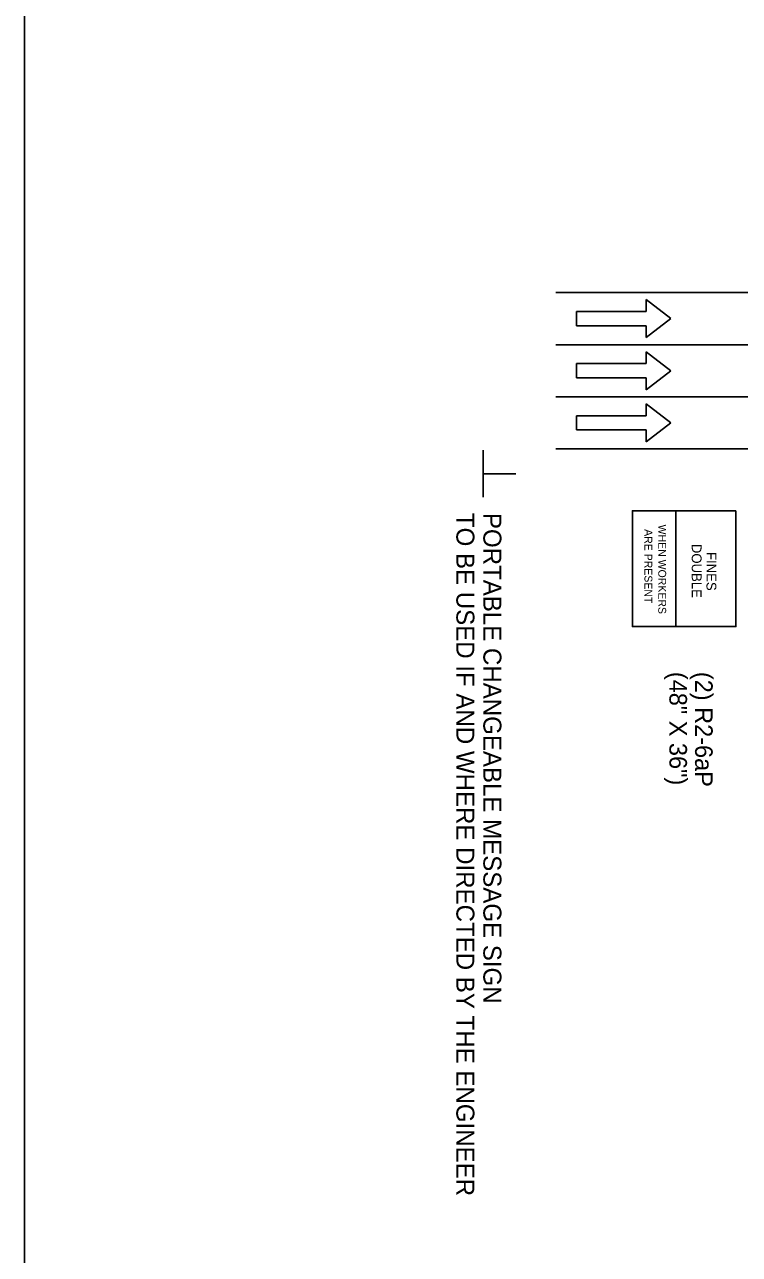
# Model space of a CAD drawing. Extents: x -100 to 745, y -1581 to -107.
# Drawn here: x 175.41 to 199.24, y -651.61 to -610.61 of the extents above; entities that cross this region are included whole.
import ezdxf

# ---------------------------------------------------------------- set-up
doc = ezdxf.new("R2010")
doc.units = 0
for name, color, linetype in [('Default', 7, 'Continuous'), ('R_Contour Annot', 7, 'Continuous'), ('R_Draft', 7, 'Continuous')]:
    doc.layers.add(name, color=color, linetype=linetype)

msp = doc.modelspace()

# ---------------------------------------------------------------- linework, layer by layer
at = {"layer": 'Default'}
for p, q in [((193.119, -619.54), (199.997, -619.54)), ((196.128, -619.777), (196.128, -620.172)), ((196.128, -619.777), (196.949, -620.409)), ((196.128, -620.172), (193.803, -620.172)), ((193.803, -620.172), (193.803, -620.646)), ((196.949, -620.409), (196.128, -621.041)), ((196.128, -620.646), (193.803, -620.646)), ((196.128, -620.646), (196.128, -621.041)), ((193.119, -621.278), (200.073, -621.278)), ((196.128, -621.515), (196.128, -621.911)), ((196.128, -621.515), (196.949, -622.148)), ((196.128, -621.911), (193.803, -621.911)), ((193.803, -621.911), (193.803, -622.385)), ((196.128, -622.385), (193.803, -622.385)), ((196.949, -622.148), (196.128, -622.78)), ((196.128, -622.385), (196.128, -622.78)), ((193.119, -623.017), (200.073, -623.017)), ((196.128, -623.254), (196.128, -623.649)), ((196.128, -623.254), (196.949, -623.886)), ((196.128, -623.649), (193.803, -623.649)), ((193.803, -623.649), (193.803, -624.123)), ((196.949, -623.886), (196.128, -624.518)), ((196.128, -624.123), (193.803, -624.123)), ((196.128, -624.123), (196.128, -624.518)), ((190.692, -626.36), (190.692, -624.795)), ((193.119, -624.755), (200.002, -624.755)), ((190.715, -625.582), (191.783, -625.582)), ((197.117, -630.677), (197.117, -626.815))]:
    msp.add_line(p, q, dxfattribs=at)
msp.add_lwpolyline([(199.119, -626.815), (195.667, -626.815), (195.667, -630.677), (199.119, -630.677)], close=True, dxfattribs=at)
at = {"layer": 'R_Contour Annot'}
msp.add_lwpolyline([(175.406, -590.582), (345.406, -590.582), (345.406, -700.582), (175.406, -700.582)], close=True, dxfattribs=at)
at = {"layer": 'R_Draft'}
msp.add_lwpolyline([(175.406, -590.582), (175.406, -700.582), (345.406, -700.582), (345.406, -590.582)], close=True, dxfattribs=at)

# ---------------------------------------------------------------- texts
at = {"layer": 'Default'}
for s, height, p in [('TO BE USED IF AND WHERE DIRECTED BY THE ENGINEER', 0.59997, (189.8, -626.888)), ('PORTABLE CHANGEABLE MESSAGE SIGN', 0.59997, (190.7, -626.888)), ('WHEN WORKERS', 0.26221, (196.531, -627.277)), ('ARE PRESENT', 0.26221, (196.071, -627.429)), ('DOUBLE', 0.3278, (197.647, -627.92)), ('FINES', 0.3278, (198.139, -628.191)), ('(48" X 36")', 0.5862, (196.902, -632.188)), ('(2) R2-6aP', 0.5862, (197.758, -632.188))]:
    msp.add_text(s, height=height, rotation=270, dxfattribs=at).set_placement(p)

doc.saveas('drawing.dxf')
